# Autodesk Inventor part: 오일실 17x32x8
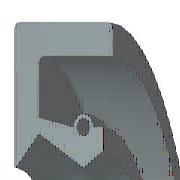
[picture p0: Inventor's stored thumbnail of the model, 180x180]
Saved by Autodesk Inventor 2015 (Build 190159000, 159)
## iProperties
IsCustomPart: 1
Company: 한국ATC센터
Created: 2014-07
Part Number: 오일실 17x32x8
Material: 고무
Description: 오일-실
Document SubType Name: Modeling
Standard: KS B 2804
Designer: KYOUNG IL JANG
Standards Organization: KS
Language: ko-KR
Size Designation: D - 17 32 8
Categories: <MemberInstance><Categories><Category DisplayName="샤프트 부품" InternalName="7f7aeb1f-a693-4053-b835-cee3144e0d98" Mnemonic="SHFT"><Category DisplayName="실링" Intern
Density: 0.93 g/cm^3
Appearance: 고무 - 검은색 - 버전 1.1
Author: KYOUNG IL JANG
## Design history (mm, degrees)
revolve "본체" stored, may be unused: angle "d17" = 90 deg
revolve "스프링1" stored, may be unused: angle "d18" = 90 deg
body "Solid1"
sketch "스케치1"
  geometry: L1 (0, 16)-(8, 16); L2 (8, 14.25)-(1.75, 14.25); L3 (1.75, 10.25)-(4.9, 8.5); L4 (4.9, 8.5)-(0, 8.5); L5 (0, 0)-(9.586, 0) reference; L6 (4.9, 8.5)-(6.3, 9.375); L7 (0, 18)-(0, -3) reference; L8 (-1.941, 0)-(11.507, 0) reference; L9 (4.2, 10.6)-(1.75, 11.21); L10 (1.75, 11.21)-(1.75, 14.25); L11 (0, 16)-(0, 8.588); L12 (4.9, 8.5)-(0, 8.5); L13 (1.75, 10.25)-(0.152, 8.528); L14 (8, 16)-(8, 14.25); L15 (5.6, 10.6)-(6.3, 10.6); L16 (6.3, 10.6)-(6.3, 9.375); C1 r 0.455 at (4.9, 10.6); A1 r 0.7 centre (4.9, 10.6) between (5.6, 10.6) and (4.2, 10.6); A2 r 0.088 centre (0.088, 8.588) between (0, 8.588) and (0.152, 8.528); 1 further point
  constraints: 28 end point, 5 horizontal alignment, 5 point on line, 4 point on circle, 4 vertical alignment, 3 centre point, 3 tangent, 2 collinear, 2 horizontal, 2 perpendicular, 1 coincident, 1 parallel
  dimensions: "d0" = 32 diameter of L1 L5 (= SD2); "d1" = 1.75 distance of L1.end L2.start (= SD); "d2" = 0.91 diameter of C1 (= SPDI); "d3" = 1.4 diameter of A1 (= SPDA); "d4" = 17 diameter of L3.end L5 (= NND); "d5" = 20.5 diameter of L3.start L5 (= TKDM); "d7" = 22.42 diameter of L9.end L5 (= TKDM + 0.24 x SWDT); "d8" = 1.75 distance between parallel lines of L11 L10 (= SD); "d9" = 4.9 distance from line of L11 C1.centre (= SPDST); "d10" = 21.2 diameter of C1.centre L5 (= HLDM); "d11" = 0.0875 radius of A2 (= 0.25 x LAB); "d12" = 6.3 distance between parallel lines of L11 L16 (= SDI); "d13" = 18.75 diameter of L6.end L5 (= ABDM); "d14" = 8 distance from line of L11 L1.end (= SWDT)
fillet "모깎기1" dims "d6" = 0.3 (= RR)
other parameters: "SD2" = 32 [user parameter; used in 1 equation term], "SWDT" = 8 [user parameter; used in 2 equation terms], "RR" = 0.3 [user parameter; used in 1 equation term], "SD" = 1.75 [user parameter; used in 2 equation terms], "NND" = 17 [user parameter; used in 1 equation term], "SPDA" = 1.4 [user parameter; used in 1 equation term], "SPDI" = 0.91 [user parameter; used in 1 equation term], "TKDM" = 20.5 [user parameter; used in 2 equation terms], "HLDM" = 21.2 [user parameter; used in 1 equation term], "ABDM" = 18.75 [user parameter; used in 1 equation term], "SDI" = 6.3 [user parameter; used in 1 equation term], "SPDST" = 4.9 [user parameter; used in 1 equation term], "LAB" = 0.35 [user parameter; used in 1 equation term], "d15" = 0, "d16" = 0, "d19" = 0
